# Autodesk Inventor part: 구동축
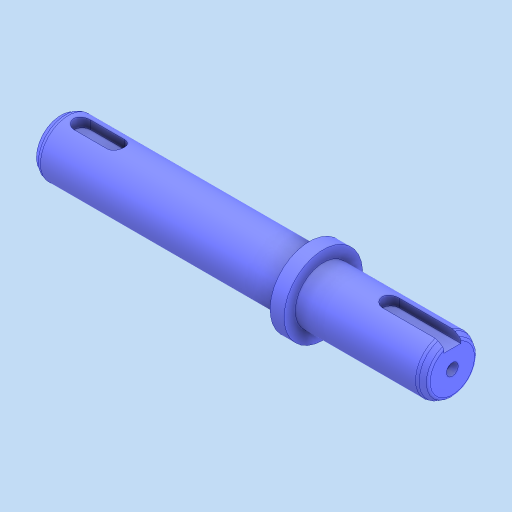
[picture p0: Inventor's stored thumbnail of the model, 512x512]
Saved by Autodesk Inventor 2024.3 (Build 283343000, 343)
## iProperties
Created: 2026-01
Part Number: 구동축
Material: 강철, 탄소
Document SubType Name: Modeling
Designer: PC2-02
Density: 7.85 g/cm^3
Appearance: 기본값
Author: jhkim
Sending System: Autodesk Inventor 2026
Preprocessor: ST-DEVELOPER v20.1
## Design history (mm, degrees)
node "구동축1"
node "솔리드2"
node "솔리드1"
